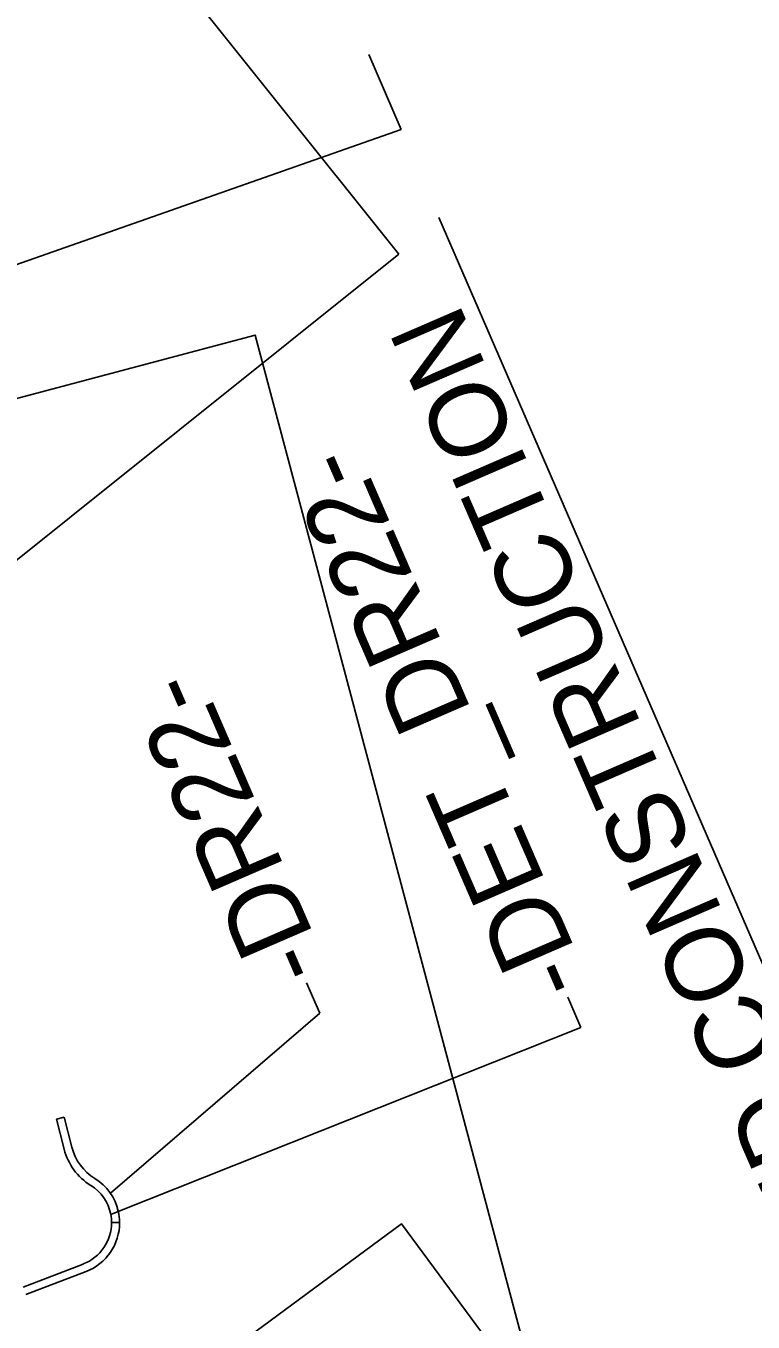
# Model space of a CAD drawing. Extents: x 442728 to 492797, y 479541 to 511293.
# Drawn here: x 474718 to 475625, y 503756 to 505372 of the extents above; entities that cross this region are included whole.
import ezdxf

# ---------------------------------------------------------------- set-up
doc = ezdxf.new("R2010")
doc.units = 0
for name, color, linetype in [('Default', 7, 'Continuous'), ('Prop DSN Text', 7, 'Continuous'), ('Prop Shade Light', 7, 'Continuous'), ('Sheet Plan Layout CELL', 7, 'Continuous')]:
    doc.layers.add(name, color=color, linetype=linetype)

msp = doc.modelspace()

# ---------------------------------------------------------------- linework, layer by layer
at = {"layer": 'Prop DSN Text'}
for p, q in [((475186.3, 505243.4), (475145.8, 505336.9)), ((475186.3, 505243.4), (474571.8, 505027.4)), ((475233.1, 505133.5), (475818.4, 503783.6)), ((475068.3, 504178.8), (475084.7, 504140.9)), ((475394.1, 504160.9), (475410.5, 504123)), ((475084.7, 504140.9), (474823.6, 503916.4)), ((475410.5, 504123), (474833.5, 503893.7))]:
    msp.add_line(p, q, dxfattribs=at)
at = {"layer": 'Prop Shade Light'}
for p, q in [((474766.1, 504011.2), (474756.4, 504008.7)), ((474756.4, 504008.7), (474766, 503971.3)), ((474775.7, 503973.7), (474766.1, 504011.2)), ((474824.1, 503889.9), (474833.5, 503893.7)), ((474833.5, 503893.7), (474824.1, 503889.9)), ((474835.1, 503879.9), (474825.1, 503879.8)), ((474825.1, 503879.8), (474835.1, 503879.9)), ((474789.8, 503828), (474714.7, 503799.2)), ((474718.3, 503789.9), (474793.4, 503818.7))]:
    msp.add_line(p, q, dxfattribs=at)
for centre, radius, start, end in [((474838.6, 503989.8), 75, 194.3457, 238.1969), ((474838.6, 503989.8), 65, 194.3457, 238.1969), ((474770.1, 503879.4), 65, 12.7383, 58.1969), ((474770.1, 503879.4), 55, 11.0962, 58.1969), ((474770.1, 503879.4), 55, 0.5074, 11.0962), ((474770.1, 503879.4), 65, 0.5074, 12.7383), ((474770.1, 503879.4), 55, 290.9632, 0.5074), ((474770.1, 503879.4), 65, 290.9632, 0.5074)]:
    msp.add_arc(centre, radius, start, end, dxfattribs=at)
at = {"layer": 'Sheet Plan Layout CELL'}
for points in [[(475183.4, 505087.7), (474363.6, 504431.6), (473660.6, 505309.9), (473660.7, 505309.9), (473426.4, 505602.7), (474246.1, 506258.8)], [(475389.4, 503537), (474374.5, 503267.4), (474085.6, 504354.7), (474085.7, 504354.7), (473989.4, 504717.1), (475004.2, 504986.7)], [(476077.7, 502671.6), (475233, 502047.8), (474564.7, 502952.8), (474564.8, 502952.8), (474342, 503254.4), (475186.7, 503878.2)]]:
    msp.add_lwpolyline(points, close=True, dxfattribs=at)

# ---------------------------------------------------------------- texts
at = {"layer": 'Default'}
msp.add_text('END TIP PROJECT R-5861', height=150, rotation=113.4424, dxfattribs=at).set_placement((476476.6, 503930.9))
at = {"layer": 'Prop DSN Text'}
for s, height, p in [('END CONSTRUCTION', 94.918, (475784.4, 503813.3)), ('-DET_DR22-', 94.92, (475420.8, 504180.5)), ('-DR22- ', 94.92, (475095, 504198.4))]:
    msp.add_text(s, height=height, rotation=113.4424, dxfattribs=at).set_placement(p)

doc.saveas('drawing.dxf')
